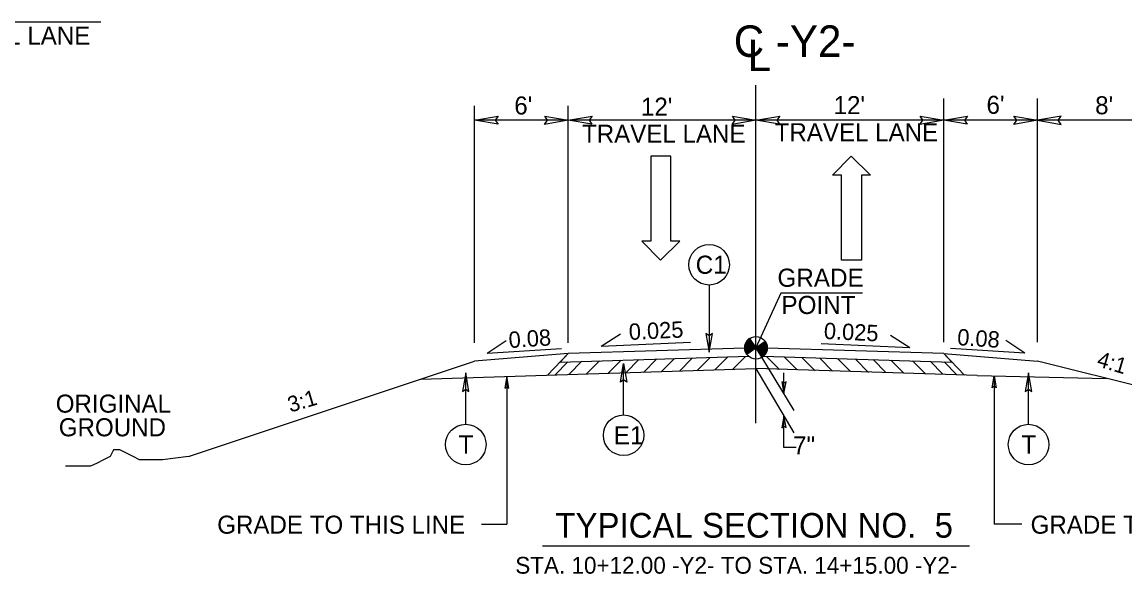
# Model space of a CAD drawing. Extents: x 2176156 to 2177167, y 76401 to 76644.
# Drawn here: x 2176264 to 2176334.6, y 76587.8 to 76623.1 of the extents above; entities that cross this region are included whole.
import ezdxf

# ---------------------------------------------------------------- set-up
doc = ezdxf.new("R2010")
doc.units = 0
for name, color, linetype in [('Exist Building', 7, 'Continuous'), ('Exist Building Metal Canopy', 7, 'Continuous'), ('Exist Roads Change in Surface', 7, 'Continuous'), ('Exist Roads Curbs', 7, 'Continuous'), ('Exist Roads EOP Other', 7, 'Continuous'), ('Exist Roads Soil', 7, 'Continuous'), ('Exist Structure Minor Culvert Topo', 7, 'Continuous'), ('Exist Structure Minor Drop Inlet', 7, 'Continuous'), ('Exist Utilities Other Pole CELL', 7, 'Continuous'), ('Exist Vegetation Woods Line', 7, 'Continuous'), ('Model Boundary Lines Text', 7, 'Continuous'), ('Old_Level_1', 7, 'Continuous'), ('Old_Level_3', 7, 'Continuous'), ('Prop North Arrow NAD83 for Plan Sheets CELL', 7, 'Continuous')]:
    doc.layers.add(name, color=color, linetype=linetype)

msp = doc.modelspace()

# ---------------------------------------------------------------- linework, layer by layer
at = {"layer": 'Exist Building'}
for p, q in [((2176289.526, 76600.285), (2176310.965, 76600.954)), ((2176325.112, 76600.513), (2176310.965, 76600.954)), ((2176325.112, 76600.513), (2176333.375, 76600.329))]:
    msp.add_line(p, q, dxfattribs=at)
at = {"layer": 'Exist Roads Change in Surface'}
for p, q in [((2176310.553, 76602.877), (2176310.965, 76602.286)), ((2176310.965, 76602.286), (2176311.556, 76602.698)), ((2176310.372, 76601.875), (2176310.965, 76602.286)), ((2176310.965, 76602.286), (2176310.372, 76601.875)), ((2176311.376, 76601.694), (2176310.965, 76602.286))]:
    msp.add_line(p, q, dxfattribs=at)
for points in [[(2176310.72, 76602.638), (2176310.244, 76602.307)], [(2176310.728, 76602.626), (2176310.244, 76602.29)], [(2176310.736, 76602.614), (2176310.244, 76602.272)], [(2176310.711, 76602.65), (2176310.245, 76602.325)], [(2176310.744, 76602.603), (2176310.245, 76602.255)], [(2176310.752, 76602.591), (2176310.245, 76602.238)], [(2176310.703, 76602.662), (2176310.246, 76602.343)], [(2176310.761, 76602.579), (2176310.247, 76602.221)], [(2176310.695, 76602.674), (2176310.248, 76602.362)], [(2176310.769, 76602.567), (2176310.248, 76602.205)], [(2176310.687, 76602.685), (2176310.25, 76602.382)], [(2176310.777, 76602.555), (2176310.25, 76602.188)], [(2176310.678, 76602.697), (2176310.252, 76602.401)], [(2176310.785, 76602.543), (2176310.253, 76602.173)], [(2176310.67, 76602.709), (2176310.256, 76602.421)], [(2176310.794, 76602.532), (2176310.256, 76602.157)], [(2176310.662, 76602.721), (2176310.261, 76602.442)], [(2176310.654, 76602.733), (2176310.266, 76602.463)], [(2176310.645, 76602.745), (2176310.272, 76602.485)], [(2176310.637, 76602.756), (2176310.278, 76602.507)], [(2176310.629, 76602.768), (2176310.286, 76602.529)], [(2176310.621, 76602.78), (2176310.295, 76602.553)], [(2176310.612, 76602.792), (2176310.305, 76602.578)], [(2176310.604, 76602.804), (2176310.318, 76602.604)], [(2176310.596, 76602.816), (2176310.332, 76602.632)], [(2176310.588, 76602.827), (2176310.348, 76602.661)], [(2176310.58, 76602.839), (2176310.368, 76602.692)], [(2176310.571, 76602.851), (2176310.395, 76602.729)], [(2176310.563, 76602.863), (2176310.429, 76602.77)], [(2176310.555, 76602.875), (2176310.49, 76602.83)], [(2176311.56, 76602.692), (2176311.56, 76602.692), (2176310.968, 76602.28)], [(2176311.568, 76602.68), (2176310.977, 76602.269)], [(2176311.575, 76602.668), (2176310.985, 76602.257)], [(2176311.583, 76602.656), (2176310.993, 76602.245)], [(2176311.59, 76602.643), (2176311.001, 76602.233)], [(2176311.597, 76602.63), (2176311.01, 76602.221)], [(2176311.604, 76602.618), (2176311.018, 76602.209)], [(2176311.611, 76602.605), (2176311.026, 76602.198)], [(2176311.618, 76602.592), (2176311.034, 76602.186)], [(2176311.624, 76602.578), (2176311.043, 76602.174)], [(2176311.629, 76602.565), (2176311.051, 76602.162)], [(2176311.635, 76602.551), (2176311.059, 76602.15)], [(2176311.641, 76602.537), (2176311.067, 76602.138)], [(2176310.802, 76602.52), (2176310.259, 76602.142)], [(2176310.81, 76602.508), (2176310.262, 76602.126)], [(2176310.818, 76602.496), (2176310.265, 76602.111)], [(2176310.827, 76602.484), (2176310.269, 76602.096)], [(2176310.835, 76602.472), (2176310.273, 76602.082)], [(2176310.843, 76602.461), (2176310.278, 76602.067)], [(2176310.851, 76602.449), (2176310.283, 76602.054)], [(2176310.86, 76602.437), (2176310.288, 76602.039)], [(2176310.868, 76602.425), (2176310.293, 76602.025)], [(2176310.876, 76602.413), (2176310.299, 76602.012)], [(2176310.884, 76602.401), (2176310.304, 76601.998)], [(2176310.892, 76602.39), (2176310.31, 76601.984)], [(2176310.901, 76602.378), (2176310.317, 76601.972)], [(2176310.909, 76602.366), (2176310.323, 76601.958)], [(2176310.917, 76602.354), (2176310.329, 76601.945)], [(2176310.925, 76602.342), (2176310.336, 76601.932)], [(2176310.934, 76602.33), (2176310.343, 76601.92)], [(2176310.942, 76602.319), (2176310.352, 76601.908)], [(2176310.95, 76602.307), (2176310.358, 76601.895)], [(2176310.958, 76602.295), (2176310.367, 76601.883), (2176310.367, 76601.883)], [(2176311.645, 76602.523), (2176311.075, 76602.127)], [(2176311.65, 76602.509), (2176311.084, 76602.115)], [(2176311.655, 76602.495), (2176311.092, 76602.103)], [(2176311.659, 76602.48), (2176311.1, 76602.091)], [(2176311.663, 76602.465), (2176311.108, 76602.079)], [(2176311.666, 76602.45), (2176311.117, 76602.067)], [(2176311.669, 76602.434), (2176311.125, 76602.056)], [(2176311.672, 76602.419), (2176311.133, 76602.044)], [(2176311.675, 76602.403), (2176311.141, 76602.032)], [(2176311.678, 76602.388), (2176311.15, 76602.02)], [(2176311.68, 76602.372), (2176311.158, 76602.008)], [(2176311.681, 76602.355), (2176311.166, 76601.996)], [(2176311.683, 76602.339), (2176311.174, 76601.985)], [(2176311.685, 76602.322), (2176311.183, 76601.973)], [(2176311.685, 76602.305), (2176311.191, 76601.961)], [(2176311.685, 76602.288), (2176311.199, 76601.949)], [(2176311.685, 76602.269), (2176311.207, 76601.937)], [(2176311.685, 76602.252), (2176311.215, 76601.925)], [(2176311.684, 76602.234), (2176311.224, 76601.914)], [(2176311.682, 76602.215), (2176311.232, 76601.902)], [(2176311.679, 76602.196), (2176311.24, 76601.89)], [(2176311.677, 76602.176), (2176311.248, 76601.878)], [(2176311.673, 76602.156), (2176311.257, 76601.866)], [(2176311.67, 76602.136), (2176311.265, 76601.854)], [(2176311.665, 76602.115), (2176311.273, 76601.843)], [(2176311.659, 76602.093), (2176311.281, 76601.831)], [(2176311.652, 76602.072), (2176311.29, 76601.819)], [(2176311.645, 76602.049), (2176311.298, 76601.807)], [(2176311.636, 76602.025), (2176311.306, 76601.795)], [(2176311.626, 76602), (2176311.314, 76601.783)], [(2176311.614, 76601.975), (2176311.322, 76601.772)], [(2176311.602, 76601.948), (2176311.331, 76601.76)], [(2176311.585, 76601.919), (2176311.339, 76601.748)], [(2176311.565, 76601.888), (2176311.347, 76601.736)], [(2176311.541, 76601.853), (2176311.355, 76601.724)], [(2176311.508, 76601.813), (2176311.364, 76601.712)], [(2176311.456, 76601.759), (2176311.372, 76601.701)]]:
    msp.add_lwpolyline(points, dxfattribs=at)
msp.add_circle((2176310.964, 76602.287), 0.721, dxfattribs=at)
for start, end in [(124.8249, 214.8249), (304.8249, 34.8249)]:
    msp.add_arc((2176310.964, 76602.287), 0.721, start, end, dxfattribs=at)
at = {"layer": 'Exist Roads Curbs'}
for p, q in [((2176310.245, 76602.238), (2176310.245, 76602.238)), ((2176310.25, 76602.188), (2176310.25, 76602.189)), ((2176310.265, 76602.111), (2176310.265, 76602.111)), ((2176310.269, 76602.096), (2176310.269, 76602.096)), ((2176310.278, 76602.067), (2176310.278, 76602.067)), ((2176310.31, 76601.984), (2176310.31, 76601.984)), ((2176310.323, 76601.958), (2176310.323, 76601.958)), ((2176310.329, 76601.945), (2176310.33, 76601.945)), ((2176310.336, 76601.932), (2176310.337, 76601.932)), ((2176310.343, 76601.92), (2176310.344, 76601.92)), ((2176310.358, 76601.895), (2176310.359, 76601.895)), ((2176310.367, 76601.883), (2176310.367, 76601.883)), ((2176310.373, 76601.875), (2176310.372, 76601.875)), ((2176310.372, 76601.875), (2176310.372, 76601.875)), ((2176298.435, 76601.368), (2176310.49, 76601.744)), ((2176311.439, 76601.744), (2176323.494, 76601.368))]:
    msp.add_line(p, q, dxfattribs=at)
for points in [[(2176310.244, 76602.263), (2176298.965, 76601.911), (2176298.435, 76601.368), (2176310.49, 76601.744)], [(2176310.245, 76602.238), (2176310.245, 76602.238)], [(2176310.25, 76602.188), (2176310.25, 76602.188)], [(2176310.265, 76602.111), (2176310.265, 76602.111)], [(2176310.269, 76602.096), (2176310.269, 76602.096)], [(2176310.278, 76602.067), (2176310.278, 76602.067)], [(2176310.31, 76601.984), (2176310.31, 76601.984)], [(2176310.323, 76601.958), (2176310.323, 76601.958)], [(2176310.33, 76601.945), (2176310.329, 76601.945)], [(2176310.337, 76601.932), (2176310.336, 76601.932)], [(2176310.344, 76601.92), (2176310.343, 76601.92)], [(2176310.359, 76601.895), (2176310.358, 76601.895)], [(2176310.367, 76601.883), (2176310.367, 76601.883)], [(2176274.681, 76595.337), (2176273.01, 76595.129), (2176272.593, 76595.129), (2176271.965, 76595.129), (2176271.548, 76595.129), (2176271.13, 76595.337), (2176270.712, 76595.547), (2176270.295, 76595.756), (2176269.877, 76595.756), (2176269.667, 76595.337), (2176269.25, 76595.129), (2176268.832, 76594.919), (2176268.414, 76594.711), (2176267.997, 76594.711), (2176267.579, 76594.711), (2176267.161, 76594.711), (2176266.822, 76594.711)]]:
    msp.add_lwpolyline(points, dxfattribs=at)
for start, end in [(181.84514, 183.8761), (183.88947, 185.20212), (185.20212, 186.51209), (186.51209, 187.80941), (187.82447, 189.07674), (189.07674, 192.8361), (192.8361, 194.07544), (194.0907, 195.29679), (195.29757, 196.50552), (196.50552, 197.7127), (197.71542, 198.88738), (198.88738, 200.09456), (200.09456, 204.78781), (204.78812, 207.10899), (207.11211, 208.26457), (208.26527, 209.41748), (209.41864, 210.56818), (210.57179, 211.71579), (211.71579, 212.8649), (212.86663, 214.01184), (214.01216, 214.77186), (214.8249, 228.84508)]:
    msp.add_arc((2176310.964, 76602.287), 0.721, start, end, dxfattribs=at)
at = {"layer": 'Exist Roads EOP Other'}
for p, q in [((2176298.965, 76601.911), (2176292.965, 76601.431)), ((2176311.541, 76601.853), (2176311.54, 76601.853)), ((2176311.565, 76601.888), (2176311.565, 76601.888)), ((2176311.585, 76601.919), (2176311.584, 76601.919)), ((2176311.602, 76601.948), (2176311.601, 76601.948)), ((2176311.614, 76601.975), (2176311.614, 76601.975)), ((2176311.645, 76602.049), (2176311.645, 76602.049)), ((2176311.652, 76602.072), (2176311.652, 76602.071)), ((2176311.665, 76602.115), (2176311.665, 76602.115)), ((2176311.67, 76602.136), (2176311.669, 76602.136)), ((2176311.673, 76602.156), (2176311.673, 76602.156)), ((2176311.677, 76602.176), (2176311.677, 76602.176)), ((2176311.684, 76602.234), (2176311.683, 76602.233)), ((2176311.685, 76602.252), (2176311.684, 76602.252)), ((2176322.965, 76601.911), (2176328.965, 76601.431)), ((2176274.681, 76595.337), (2176292.965, 76601.431)), ((2176311.456, 76601.759), (2176311.455, 76601.759)), ((2176311.508, 76601.813), (2176311.508, 76601.813)), ((2176336.917, 76599.444), (2176328.965, 76601.431))]:
    msp.add_line(p, q, dxfattribs=at)
for points in [[(2176311.439, 76601.744), (2176323.494, 76601.368), (2176322.965, 76601.911), (2176311.685, 76602.263)], [(2176311.541, 76601.853), (2176311.541, 76601.853)], [(2176311.565, 76601.888), (2176311.565, 76601.888)], [(2176311.585, 76601.919), (2176311.585, 76601.919)], [(2176311.601, 76601.949), (2176311.602, 76601.948)], [(2176311.614, 76601.975), (2176311.614, 76601.975)], [(2176311.645, 76602.049), (2176311.645, 76602.049)], [(2176311.652, 76602.072), (2176311.652, 76602.072)], [(2176311.665, 76602.115), (2176311.665, 76602.115)], [(2176311.669, 76602.136), (2176311.67, 76602.136)], [(2176311.673, 76602.156), (2176311.673, 76602.156)], [(2176311.677, 76602.177), (2176311.677, 76602.176)], [(2176311.683, 76602.234), (2176311.684, 76602.234)], [(2176311.684, 76602.252), (2176311.685, 76602.252)], [(2176311.456, 76601.759), (2176311.456, 76601.759)], [(2176311.508, 76601.813), (2176311.508, 76601.813)]]:
    msp.add_lwpolyline(points, dxfattribs=at)
for start, end in [(318.962, 323.02167), (323.07123, 326.39495), (326.45695, 329.32655), (329.36485, 331.96034), (332.04132, 334.37636), (334.38027, 340.73102), (340.73681, 342.64285), (342.64598, 344.4557), (344.4557, 346.24045), (346.26481, 347.94552), (347.9775, 349.59802), (349.59837, 351.20379), (351.21961, 354.28369), (354.28369, 355.7778), (355.81267, 357.23939), (357.26518, 358.16121), (311.15703, 312.91767), (312.99666, 318.89175)]:
    msp.add_arc((2176310.964, 76602.287), 0.721, start, end, dxfattribs=at)
at = {"layer": 'Exist Roads Soil'}
for p, q in [((2176298.965, 76601.911), (2176297.628, 76600.538)), ((2176322.965, 76601.911), (2176324.302, 76600.538))]:
    msp.add_line(p, q, dxfattribs=at)
at = {"layer": 'Exist Structure Minor Drop Inlet'}
for p, q in [((2176304.24, 76614.543), (2176304.24, 76609.111)), ((2176305.52, 76614.543), (2176304.24, 76614.543)), ((2176305.52, 76609.111), (2176305.52, 76614.543)), ((2176315.85, 76613.321), (2176317.053, 76614.543)), ((2176317.053, 76614.543), (2176318.295, 76613.321)), ((2176316.432, 76613.321), (2176315.85, 76613.321)), ((2176316.432, 76607.889), (2176316.432, 76613.321)), ((2176318.295, 76613.321), (2176317.713, 76613.321)), ((2176317.713, 76613.321), (2176317.713, 76607.889)), ((2176304.24, 76609.111), (2176303.658, 76609.111)), ((2176303.658, 76609.111), (2176304.86, 76607.889)), ((2176304.86, 76607.889), (2176306.102, 76609.111)), ((2176306.102, 76609.111), (2176305.52, 76609.111)), ((2176317.713, 76607.889), (2176316.432, 76607.889))]:
    msp.add_line(p, q, dxfattribs=at)
at = {"layer": 'Exist Utilities Other Pole CELL'}
for p, q in [((2176293.772, 76601.935), (2176294.997, 76602.754)), ((2176301.071, 76602.379), (2176302.311, 76603.174)), ((2176301.071, 76602.379), (2176306.781, 76602.645)), ((2176320.8, 76602.276), (2176315.138, 76602.54)), ((2176320.8, 76602.276), (2176319.56, 76603.072)), ((2176328.157, 76601.935), (2176326.933, 76602.754)), ((2176293.772, 76601.935), (2176298.518, 76602.249)), ((2176328.157, 76601.935), (2176323.411, 76602.249))]:
    msp.add_line(p, q, dxfattribs=at)
at = {"layer": 'Model Boundary Lines Text'}
for p, q in [((2176298.123, 76600.559), (2176298.937, 76601.382)), ((2176299.016, 76600.592), (2176299.838, 76601.424)), ((2176300.135, 76600.614), (2176300.957, 76601.446)), ((2176301.518, 76600.655), (2176302.34, 76601.487)), ((2176302.656, 76600.696), (2176303.479, 76601.53)), ((2176303.775, 76600.716), (2176304.597, 76601.549)), ((2176304.924, 76600.762), (2176305.749, 76601.598)), ((2176306.064, 76600.795), (2176306.883, 76601.625)), ((2176307.186, 76600.822), (2176308.008, 76601.653)), ((2176308.336, 76600.873), (2176309.16, 76601.707)), ((2176309.461, 76600.901), (2176310.288, 76601.738)), ((2176312.469, 76600.901), (2176311.642, 76601.738)), ((2176313.594, 76600.873), (2176312.769, 76601.707)), ((2176314.743, 76600.822), (2176313.921, 76601.653)), ((2176315.866, 76600.795), (2176315.047, 76601.625)), ((2176317.006, 76600.762), (2176316.18, 76601.598)), ((2176318.155, 76600.716), (2176317.333, 76601.549)), ((2176319.274, 76600.696), (2176318.45, 76601.53)), ((2176320.412, 76600.655), (2176319.59, 76601.487)), ((2176321.794, 76600.614), (2176320.972, 76601.446)), ((2176322.913, 76600.592), (2176322.091, 76601.424)), ((2176323.806, 76600.559), (2176322.993, 76601.382)), ((2176297.304, 76589.618), (2176324.625, 76589.618))]:
    msp.add_line(p, q, dxfattribs=at)
at = {"layer": 'Old_Level_1'}
for points in [[(2176294.474, 76616.572), (2176292.965, 76616.832), (2176294.483, 76617.101), (2176294.29, 76616.832)], [(2176297.455, 76617.092), (2176298.965, 76616.832), (2176297.447, 76616.564), (2176297.64, 76616.832)], [(2176300.474, 76616.572), (2176298.965, 76616.832), (2176300.483, 76617.101), (2176300.29, 76616.832)], [(2176309.455, 76617.092), (2176310.965, 76616.832), (2176309.447, 76616.564), (2176309.64, 76616.832)], [(2176312.474, 76616.572), (2176310.965, 76616.832), (2176312.483, 76617.101), (2176312.29, 76616.832)], [(2176321.455, 76617.092), (2176322.965, 76616.832), (2176321.447, 76616.564), (2176321.64, 76616.832)], [(2176324.474, 76616.572), (2176322.965, 76616.832), (2176324.483, 76617.101), (2176324.29, 76616.832)], [(2176327.455, 76617.092), (2176328.965, 76616.832), (2176327.447, 76616.564), (2176327.64, 76616.832)], [(2176330.474, 76617.092), (2176328.965, 76616.832), (2176330.483, 76616.564), (2176330.29, 76616.832)], [(2176295.162, 76599.702), (2176295.032, 76600.457), (2176294.897, 76599.698), (2176295.032, 76599.794)], [(2176326.063, 76599.734), (2176326.193, 76600.489), (2176326.327, 76599.73), (2176326.193, 76599.826)], [(2176312.621, 76600.108), (2176312.753, 76599.353), (2176312.885, 76600.112), (2176312.751, 76600.016)], [(2176312.885, 76597.18), (2176312.753, 76597.934), (2176312.621, 76597.175), (2176312.755, 76597.272)]]:
    msp.add_lwpolyline(points, close=True, dxfattribs=at)
at = {"layer": 'Old_Level_3'}
for p, q in [((2176269.07, 76623.109), (2176257.176, 76623.109)), ((2176310.965, 76614.269), (2176310.965, 76619.072)), ((2176322.965, 76602.644), (2176322.965, 76618.228)), ((2176328.965, 76602.644), (2176328.965, 76618.228)), ((2176292.965, 76602.6), (2176292.965, 76617.76)), ((2176298.965, 76602.6), (2176298.965, 76617.76)), ((2176298.965, 76616.832), (2176292.965, 76616.832)), ((2176310.965, 76616.832), (2176299.071, 76616.832)), ((2176322.965, 76616.832), (2176310.965, 76616.832)), ((2176336.965, 76616.832), (2176322.965, 76616.832)), ((2176310.965, 76597.466), (2176310.965, 76614.269)), ((2176310.965, 76602.286), (2176313.39, 76598.278)), ((2176295.032, 76600.457), (2176295.032, 76591.005)), ((2176310.965, 76600.954), (2176313.39, 76596.859)), ((2176312.753, 76599.353), (2176312.753, 76600.681)), ((2176326.193, 76600.489), (2176326.193, 76591.005)), ((2176312.753, 76595.921), (2176312.753, 76597.934)), ((2176313.533, 76595.921), (2176312.753, 76595.921)), ((2176293.406, 76591.005), (2176295.032, 76591.005)), ((2176327.96, 76591.005), (2176326.193, 76591.005))]:
    msp.add_line(p, q, dxfattribs=at)
at = {"layer": 'Prop North Arrow NAD83 for Plan Sheets CELL'}
for p, q in [((2176307.967, 76606.299), (2176307.967, 76601.996)), ((2176312.558, 76605.78), (2176310.965, 76602.286)), ((2176317.777, 76605.78), (2176312.558, 76605.78)), ((2176302.502, 76597.99), (2176302.502, 76601.286)), ((2176292.405, 76597.395), (2176292.405, 76600.691)), ((2176328.392, 76597.395), (2176328.392, 76600.691))]:
    msp.add_line(p, q, dxfattribs=at)
for points in [[(2176307.76, 76603.196), (2176307.967, 76601.996), (2176308.18, 76603.203), (2176307.967, 76603.05)], [(2176302.295, 76600.086), (2176302.502, 76601.286), (2176302.715, 76600.079), (2176302.502, 76600.232)], [(2176292.612, 76599.491), (2176292.405, 76600.691), (2176292.192, 76599.484), (2176292.405, 76599.637)], [(2176328.599, 76599.491), (2176328.392, 76600.691), (2176328.179, 76599.484), (2176328.392, 76599.637)]]:
    msp.add_lwpolyline(points, close=True, dxfattribs=at)
for centre in [(2176307.967, 76607.595), (2176302.502, 76596.694), (2176292.405, 76596.099), (2176328.392, 76596.099)]:
    msp.add_circle(centre, 1.296, dxfattribs=at)

# ---------------------------------------------------------------- texts
at = {"layer": 'Exist Building Metal Canopy'}
msp.add_text('TYPICAL SECTION NO.  5', height=1.5766, rotation=0.00002, dxfattribs=at).set_placement((2176298.137, 76590.146))
at = {"layer": 'Exist Roads Curbs'}
for s, rotation, p in [('4:1', 343.53506, (2176332.702, 76601.119)), ('3:1', 16.46494, (2176281.188, 76598.138))]:
    msp.add_text(s, height=1.0064, rotation=rotation, dxfattribs=at).set_placement(p)
at = {"layer": 'Exist Structure Minor Culvert Topo'}
for s, height, p in [('TRAVEL LANE', 1.15334, (2176257.944, 76621.667)), ("6'", 1.1533, (2176295.51, 76617.199)), ("12'", 1.1533, (2176303.609, 76617.121)), ("12'", 1.1533, (2176315.927, 76617.221)), ("6'", 1.1533, (2176325.704, 76617.241)), ("8'", 1.1533, (2176332.652, 76617.213)), ('TRAVEL LANE', 1.15334, (2176312.157, 76615.491)), ('TRAVEL LANE', 1.15334, (2176299.839, 76615.391)), ('ORIGINAL', 1.1533, (2176266.19, 76598.139)), ('GROUND', 1.1533, (2176266.384, 76596.627)), ('GRADE TO THIS LINE', 1.15334, (2176276.514, 76590.401)), ('GRADE TO THIS LINE', 1.15334, (2176328.523, 76590.401))]:
    msp.add_text(s, height=height, dxfattribs=at).set_placement(p)
at = {"layer": 'Exist Utilities Other Pole CELL'}
for s, rotation, p in [('0.025', 2.6676, (2176302.857, 76602.784)), ('0.08', 3.78012, (2176295.182, 76602.265)), ('0.025 ', 357.3324, (2176315.287, 76602.855)), ('0.08', 356.21988, (2176323.807, 76602.459))]:
    msp.add_text(s, height=1.0429, rotation=rotation, dxfattribs=at).set_placement(p)
at = {"layer": 'Exist Vegetation Woods Line'}
for s, height, p in [('C -Y2-', 2.0131, (2176309.544, 76620.882)), ('STA. 10+12.00 -Y2- TO STA. 14+15.00 -Y2-', 1.0742, (2176295.574, 76587.843))]:
    msp.add_text(s, height=height, dxfattribs=at).set_placement(p)
msp.add_text('L', height=2.013, rotation=359.9469, dxfattribs=at).set_placement((2176310.422, 76619.981))
at = {"layer": 'Prop North Arrow NAD83 for Plan Sheets CELL'}
for s, rotation, p in [('C1', 359.99974, (2176307.11, 76607.015)), ('GRADE', 0.00015, (2176312.336, 76606.185)), ('POINT', 0.00015, (2176312.589, 76604.445)), ('E1', 0.00026, (2176301.874, 76596.114)), ('T', 359.99974, (2176291.948, 76595.519)), ('T', 359.99974, (2176327.935, 76595.519))]:
    msp.add_text(s, height=1.16, rotation=rotation, dxfattribs=at).set_placement(p)
msp.add_text('7"', height=1.1533, dxfattribs=at).set_placement((2176313.338, 76595.471))

doc.saveas('drawing.dxf')
